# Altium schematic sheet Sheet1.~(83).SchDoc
size A
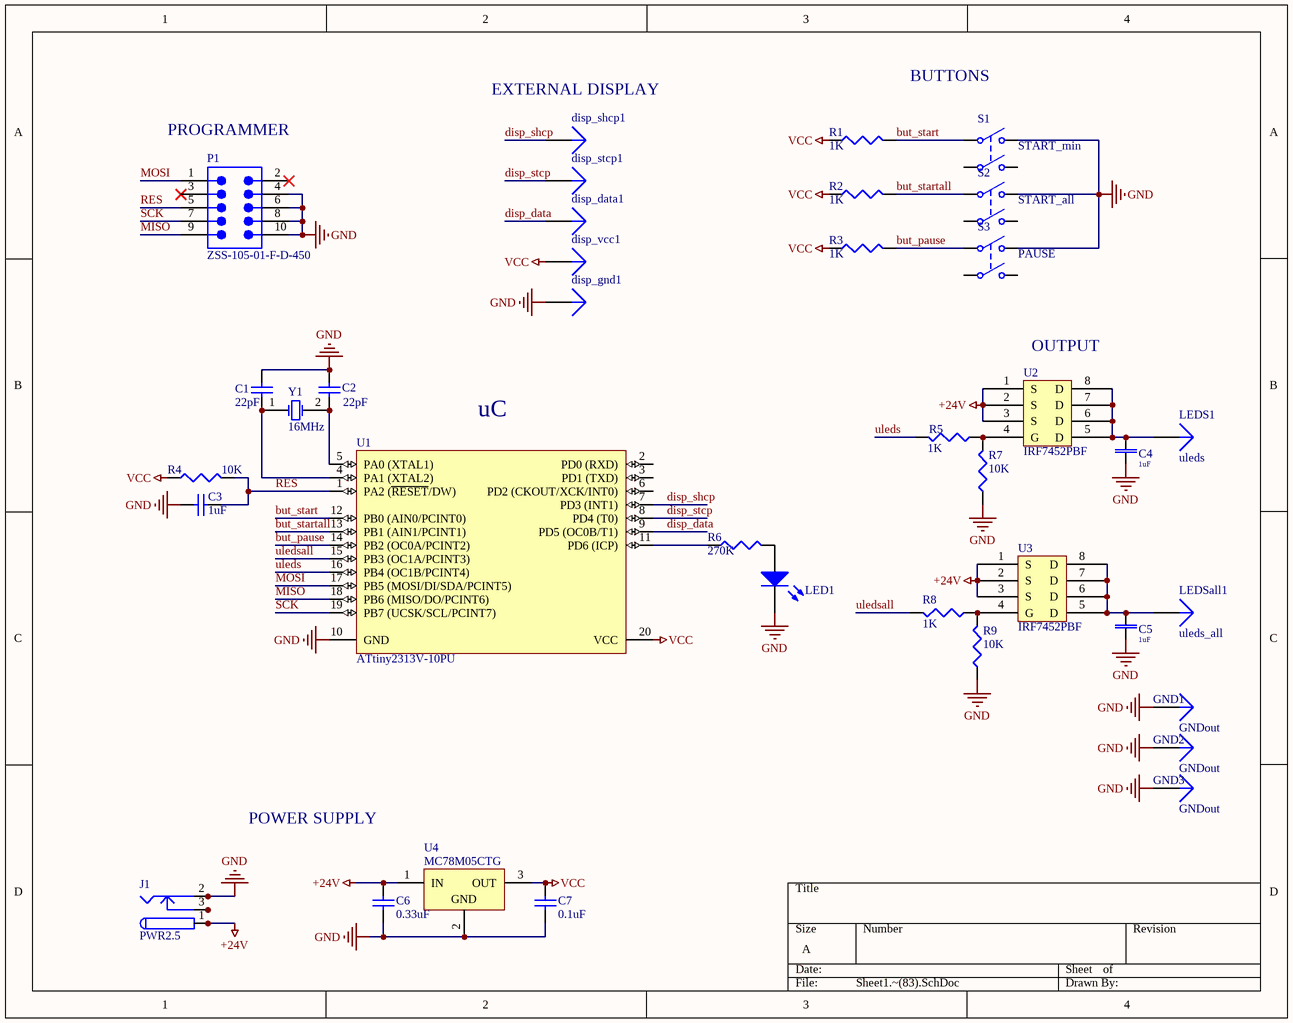
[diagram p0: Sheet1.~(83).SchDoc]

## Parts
C1  value 22pF  [CAPC1608L]  (hidden comment: Cap Semi)
C2  value 22pF  [CAPC1608L]  (hidden comment: Cap Semi)
C3  value 1uF  [CAPC1608L]  (hidden comment: Cap Semi)
C4  value 1uF  [CAPC3216L]  (hidden comment: Cap Semi)
C5  value 1uF  [CAPC3216L]  (hidden comment: Cap Semi)
C6  value 0.33uF  [CAPC1608L]  (hidden comment: Cap Semi)
C7  value 0.1uF  [CAPC1608L]  (hidden comment: Cap Semi)
disp_data1  uleds_all  [PIN1]  (value not drawn)
disp_gnd1  uleds_all  [PIN1]  (value not drawn)
disp_shcp1  uleds_all  [PIN1]  (value not drawn)
disp_stcp1  uleds_all  [PIN1]  (value not drawn)
disp_vcc1  uleds_all  [PIN1]  (value not drawn)
GND1  GNDout  [PIN1]
GND2  GNDout  [PIN1]
GND3  GNDout  [PIN1]
J1  PWR2.5  [PCBComponent_1]
LED1  151051YS04000  [Type 5mm]  (value not drawn)
LEDS1  uleds  [PIN1]
LEDSall1  uleds_all  [PIN1]
P1  ZSS-105-01-F-D-450  [SMTC-ZSS-105-01-X-D-450]
R1  value 1K  [CAPC1608L]  (hidden comment: Res3)
R2  value 1K  [CAPC1608L]  (hidden comment: Res3)
R3  value 1K  [CAPC1608L]  (hidden comment: Res3)
R4  value 10K  [CAPC1608L]  (hidden comment: Res3)
R5  value 1K  [CAPC1608L]  (hidden comment: Res3)
R6  value 270K  [CAPC1608L]  (hidden comment: Res3)
R7  value 10K  [CAPC1608L]  (hidden comment: Res3)
R8  value 1K  [CAPC1608L]  (hidden comment: Res3)
R9  value 10K  [CAPC1608L]  (hidden comment: Res3)
S1  START_min  [key]
S2  START_all  [key]
S3  PAUSE  [key]
U1  ATtiny2313V-10PU  [20P3]
U2  IRF7452PBF  [SO-8_M]
U3  IRF7452PBF  [SO-8_M]
U4  MC78M05CTG  [TO220]
Y1  16MHz  [PCBComponent_1 - duplicate]

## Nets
+24V: C6.2 J1.1 J1.1A J1.1B U2.1(S) U2.2(S) U2.3(S) U3.1(S) U3.2(S) U3.3(S) U4.1(IN)
GND: C1.1 C2.1 C3.2 C4.2 C5.2 C6.1 C7.1 disp_gnd1.1 GND1.1 GND2.1 GND3.1 J1.2 J1.2A J1.2B LED1.1(K) P1.4 P1.6 P1.8 P1.10 R7.1 R9.1 S1.2(NO1) S2.2(NO1) S3.2(NO1) U1.10(GND) U4.2(GND)
VCC: C7.2 disp_vcc1.1 R1.1 R2.1 R3.1 R4.1 U1.20(VCC) U4.3(OUT)
but_pause: R3.2 S3.1(COMMON1) U1.14(PB2_(OC0A/PCINT2))
but_start: R1.2 S1.1(COMMON1) U1.12(PB0_(AIN0/PCINT0))
but_startall: R2.2 S2.1(COMMON1) U1.13(PB1_(AIN1/PCINT1))
disp_data: disp_data1.1 U1.9(PD5_(OC0B/T1))
disp_shcp: disp_shcp1.1 U1.7(PD3_(INT1))
disp_stcp: disp_stcp1.1 U1.8(PD4_(T0))
MISO: P1.9 U1.18(PB6_(MISO/DO/PCINT6))
MOSI: P1.1 U1.17(PB5_(MOSI/DI/SDA/PCINT5))
RES: C3.1 P1.5 R4.2 U1.1(PA2_(~{RESET}/DW))
SCK: P1.7 U1.19(PB7_(UCSK/SCL/PCINT7))
uleds: R5.2 U1.16(PB4_(OC1B/PCINT4))
uledsall: R8.2 U1.15(PB3_(OC1A/PCINT3))
NetC1_2: C1.2 U1.4(PA1_(XTAL2)) Y1.1(OSC1)
NetC2_2: C2.2 U1.5(PA0_(XTAL1)) Y1.2(OSC2)
NetC4_1: C4.1 LEDS1.1 U2.5(D) U2.6(D) U2.7(D) U2.8(D)
NetC5_1: C5.1 LEDSall1.1 U3.5(D) U3.6(D) U3.7(D) U3.8(D)
NetJ1_3: J1.3 J1.3A J1.3B
NetLED1_2: LED1.2(A) R6.2
NetR5_1: R5.1 R7.2 U2.4(G)
NetR6_1: R6.1 U1.11(PD6_(ICP))
NetR8_1: R8.1 R9.2 U3.4(G)

Not connected (* = marked no-connect by the designer): P1 2* 3*; S1 3(COMMON2) 4(NO2); S2 3(COMMON2) 4(NO2); S3 3(COMMON2) 4(NO2); U1 2(PD0_(RXD)) 3(PD1_(TXD)) 6(PD2_(CKOUT/XCK/INT0))

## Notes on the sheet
- (near disp_shcp1) EXTERNAL DISPLAY
- BUTTONS
- (near P1) PROGRAMMER
- (near U2) OUTPUT
- (near U1) uC
- POWER SUPPLY

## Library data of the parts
C1-C7 = Cap Semi: Capacitor (Semiconductor SIM Model)
disp_data1 disp_gnd1 disp_shcp1 disp_stcp1 disp_vcc1 GND1-GND3 LEDS1 LEDSall1 = Plug
J1 = PWR2.5: Low Voltage Power Supply Connector
LED1 = CMP-1488-00010-1: THT LED round mono-color color lens, WL-TMRW, Yellow; Manufacturer: Wuerth Elektronik
P1 = CMP-1024-00461-1: Manufacturer: Samtec; Pitch: 2.54 mm
R1-R9 = Res3: Resistor
S1-S3 = SW-DPST: Double-Pole, Single-Throw Switch
U1 = CMP-0093-00017-1: Low Power tinyAVR® 8-Bit Microcontroller, 2K Flash Memory, 10MHz, Industrial Temperature, 20-Lead PDIP, Pb-Free
U4 = CMP-0244-00483-1: Positive Voltage Regulator, 5V, 3-Pin TO-220
Y1 = XTAL: Crystal Oscillator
